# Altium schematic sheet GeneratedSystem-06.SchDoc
size 186 x 83 mm
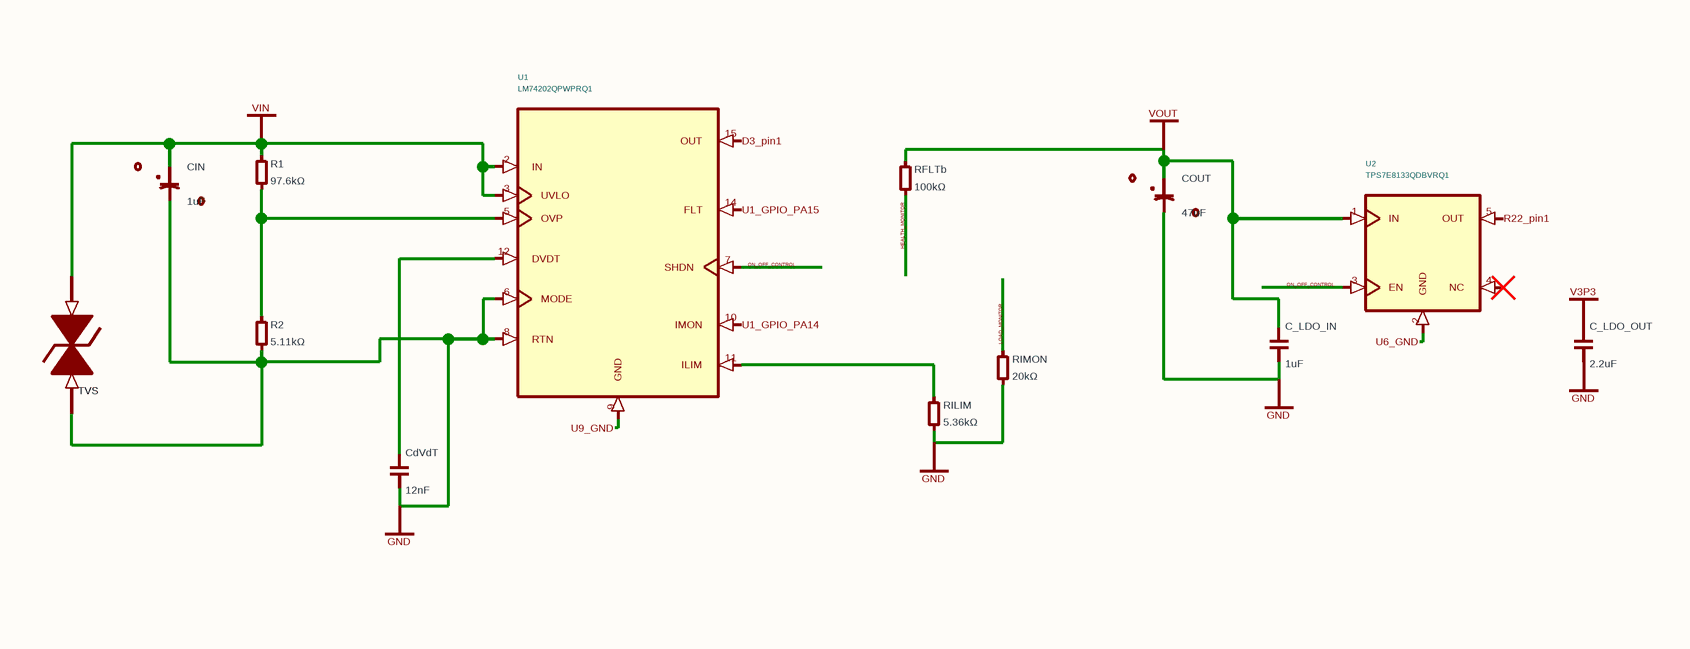
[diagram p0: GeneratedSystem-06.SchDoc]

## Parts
C_LDO_IN  1uF
C_LDO_OUT  2.2uF
CdVdT  12nF
CIN  1uF
COUT  47uF
R1  97.6kΩ
R2  5.11kΩ
RFLTb  100kΩ
RILIM  5.36kΩ
RIMON  20kΩ
TVS  (no value)
U1  (no value)
U2  (no value)

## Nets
GND: C_LDO_IN.2(cathode) C_LDO_OUT.2(cathode) CdVdT.2(cathode) CIN.2(neg) COUT.2(neg) R2.2(cathode) RILIM.2(cathode) RIMON.2(cathode) TVS.1(pin1) U1.6(MODE) U1.8(RTN)
V3P3: C_LDO_OUT.1(anode)
VIN: CIN.1(pos) R1.1(anode) TVS.2(pin2) U1.2(IN) U1.3(UVLO)
VOUT: C_LDO_IN.1(anode) COUT.1(pos) RFLTb.1(anode) U2.1(IN)
D3_pin1: U1.15(OUT)
R22_pin1: U2.5(OUT)
U1_GPIO_PA14: U1.10(IMON)
U1_GPIO_PA15: U1.14(FLT)
U6_GND: U2.2(GND)
U9_GND: U1.9(GND)
NetCdVdT_1: CdVdT.1(anode) U1.12(DVDT)
NetR1_2: R1.2(cathode) R2.1(anode) U1.5(OVP)
NetRILIM_1: RILIM.1(anode) U1.11(ILIM)

Not connected (* = marked no-connect by the designer): RFLTb 2(cathode); RIMON 1(anode); U1 7(SHDN); U2 3(EN) 4(NC)*

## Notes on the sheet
- (near U1) ON_OFF_CONTROL
- (near RFLTb) HEALTH_MONITOR
- (near U2) ON_OFF_CONTROL
- (near RIMON) LOAD_MONITOR

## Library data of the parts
C_LDO_IN C_LDO_OUT CdVdT = capacitor_down
CIN COUT = capacitor_polarized_down
R1 R2 RFLTb RILIM RIMON = boxresistor_down
TVS = TVS
U1 = U1
U2 = U2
